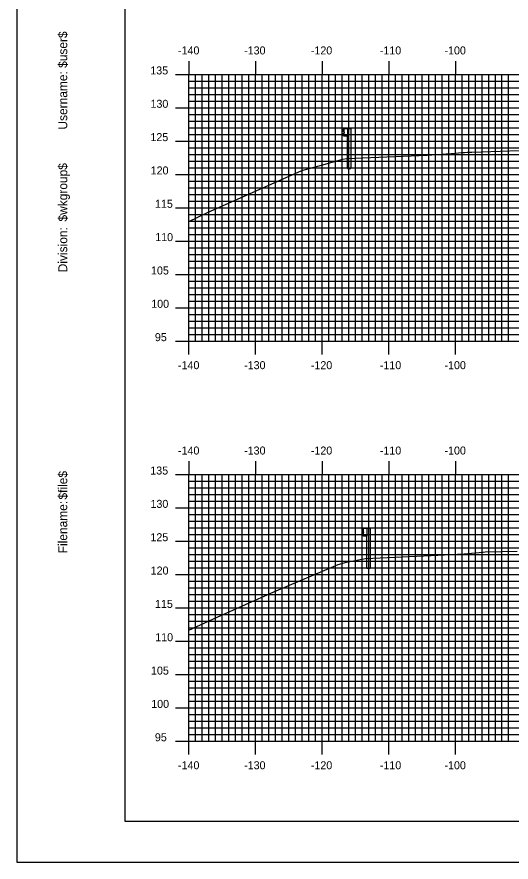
# Model space of a CAD drawing. Extents: x 858445 to 858788, y 364366 to 364586.
# Drawn here: x 858445.1 to 858519.2, y 364365.7 to 364492.4 of the extents above; entities that cross this region are included whole.
import ezdxf

# ---------------------------------------------------------------- set-up
doc = ezdxf.new("R2010")
doc.units = 0
for name, color, linetype in [('BORDER', 7, 'Continuous'), ('H_V ANNOTATION', 7, 'Continuous'), ('M_Guardrail', 7, 'Continuous'), ('M_Roadway_Centerline', 7, 'Continuous'), ('MAJOR', 7, 'Continuous'), ('MINOR', 7, 'Continuous'), ('PLOT BOUNDARY', 7, 'Continuous'), ('S_Roadway_Centerline', 7, 'Continuous')]:
    doc.layers.add(name, color=color, linetype=linetype)

msp = doc.modelspace()

# ---------------------------------------------------------------- linework, layer by layer
at = {"layer": 'BORDER'}
msp.add_lwpolyline([(858461.27, 364371.79), (858781.27, 364371.79), (858781.27, 364581.79), (858461.27, 364581.79)], close=True, dxfattribs=at)
at = {"layer": 'M_Guardrail'}
for p, q in [((858494.11, 364475.58), (858493.97, 364475.48)), ((858493.97, 364475.34), (858494.17, 364475.2)), ((858494.21, 364475.6), (858494.13, 364475.59)), ((858494.21, 364475.68), (858494.7, 364475.68)), ((858494.21, 364474.51), (858494.21, 364475.68)), ((858494.7, 364475.68), (858495.19, 364475.68)), ((858494.7, 364475.68), (858494.7, 364474.51)), ((858495.19, 364475.68), (858495.19, 364469.68)), ((858494.17, 364474.98), (858493.97, 364474.85)), ((858493.97, 364474.7), (858494.11, 364474.6)), ((858494.13, 364474.6), (858494.21, 364474.58)), ((858494.2, 364475.14), (858494.2, 364475.05)), ((858494.7, 364474.51), (858494.21, 364474.51)), ((858494.7, 364469.68), (858494.7, 364474.51)), ((858494.7, 364469.68), (858495.19, 364469.68)), ((858497.1, 364415.73), (858497.59, 364415.73)), ((858497.1, 364414.57), (858497.1, 364415.73)), ((858497.59, 364415.73), (858498.08, 364415.73)), ((858497.59, 364415.73), (858497.59, 364414.57)), ((858498.08, 364415.73), (858498.08, 364409.73)), ((858497, 364415.64), (858496.85, 364415.54)), ((858496.85, 364415.4), (858497.05, 364415.26)), ((858497.05, 364415.04), (858496.85, 364414.9)), ((858496.85, 364414.76), (858497, 364414.66)), ((858497.1, 364415.66), (858497.02, 364415.65)), ((858497.02, 364414.65), (858497.1, 364414.64)), ((858497.08, 364415.2), (858497.08, 364415.1)), ((858497.59, 364414.57), (858497.1, 364414.57)), ((858497.59, 364409.73), (858497.59, 364414.57)), ((858497.59, 364409.73), (858498.08, 364409.73))]:
    msp.add_line(p, q, dxfattribs=at)
for centre, major_axis, start_param, end_param in [((858494.02, 364475.41), (-0.0877, 0), 5.323254, 7.243116), ((858494.14, 364475.55), (-0.0417, 0), 4.886922, 5.323254), ((858494.02, 364474.78), (-0.0877, 0), 5.323254, 7.243116), ((858494.14, 364474.64), (-0.0417, 0), 0.959931, 1.396263), ((858494.12, 364475.14), (0.0789, 0), 0, 0.959931), ((858494.12, 364475.05), (0.0789, 0), 5.323254, 6.283185), ((858496.91, 364415.47), (-0.0877, 0), 5.323254, 7.243116), ((858496.91, 364414.83), (-0.0877, 0), 5.323254, 7.243116), ((858497.02, 364415.61), (-0.0417, 0), 4.886922, 5.323254), ((858497.02, 364414.69), (-0.0417, 0), 0.959931, 1.396263), ((858497, 364415.2), (0.0789, 0), 0, 0.959931), ((858497, 364415.1), (0.0789, 0), 5.323254, 6.283185)]:
    msp.add_ellipse(centre, major_axis=major_axis, ratio=0.995501, start_param=start_param, end_param=end_param, dxfattribs=at)
at = {"layer": 'MAJOR'}
for p, q in [((858470.87, 364485.79), (858470.87, 364483.79)), ((858480.87, 364485.79), (858480.87, 364483.79)), ((858490.87, 364485.79), (858490.87, 364483.79)), ((858500.87, 364485.79), (858500.87, 364483.79)), ((858510.87, 364485.79), (858510.87, 364483.79)), ((858468.87, 364483.79), (858470.87, 364483.79)), ((858470.87, 364483.79), (858750.87, 364483.79)), ((858470.87, 364443.79), (858470.87, 364483.79)), ((858470.87, 364443.79), (858470.87, 364483.79)), ((858470.87, 364483.79), (858750.87, 364483.79)), ((858480.87, 364443.79), (858480.87, 364483.79)), ((858490.87, 364443.79), (858490.87, 364483.79)), ((858500.87, 364443.79), (858500.87, 364483.79)), ((858510.87, 364443.79), (858510.87, 364483.79)), ((858468.87, 364478.79), (858470.87, 364478.79)), ((858470.87, 364478.79), (858750.87, 364478.79)), ((858468.87, 364473.79), (858470.87, 364473.79)), ((858470.87, 364473.79), (858750.87, 364473.79)), ((858468.87, 364468.79), (858470.87, 364468.79)), ((858470.87, 364468.79), (858750.87, 364468.79)), ((858468.87, 364463.79), (858470.87, 364463.79)), ((858470.87, 364463.79), (858750.87, 364463.79)), ((858468.87, 364458.79), (858470.87, 364458.79)), ((858470.87, 364458.79), (858750.87, 364458.79)), ((858468.87, 364453.79), (858470.87, 364453.79)), ((858470.87, 364453.79), (858750.87, 364453.79)), ((858468.87, 364448.79), (858470.87, 364448.79)), ((858470.87, 364448.79), (858750.87, 364448.79)), ((858468.87, 364443.79), (858470.87, 364443.79)), ((858470.87, 364443.79), (858750.87, 364443.79)), ((858470.87, 364443.79), (858750.87, 364443.79)), ((858470.87, 364441.78), (858470.87, 364443.79)), ((858480.87, 364441.78), (858480.87, 364443.79)), ((858490.87, 364441.78), (858490.87, 364443.79)), ((858500.87, 364441.78), (858500.87, 364443.79)), ((858510.87, 364441.78), (858510.87, 364443.79)), ((858470.87, 364425.79), (858470.87, 364423.79)), ((858480.87, 364425.79), (858480.87, 364423.79)), ((858490.87, 364425.79), (858490.87, 364423.79)), ((858500.87, 364425.79), (858500.87, 364423.79)), ((858510.87, 364425.79), (858510.87, 364423.79)), ((858468.87, 364423.79), (858470.87, 364423.79)), ((858470.87, 364423.79), (858750.87, 364423.79)), ((858470.87, 364383.79), (858470.87, 364423.79)), ((858470.87, 364383.79), (858470.87, 364423.79)), ((858470.87, 364423.79), (858750.87, 364423.79)), ((858480.87, 364383.79), (858480.87, 364423.79)), ((858490.87, 364383.79), (858490.87, 364423.79)), ((858500.87, 364383.79), (858500.87, 364423.79)), ((858510.87, 364383.79), (858510.87, 364423.79)), ((858468.87, 364418.79), (858470.87, 364418.79)), ((858470.87, 364418.79), (858750.87, 364418.79)), ((858468.87, 364413.79), (858470.87, 364413.79)), ((858470.87, 364413.79), (858750.87, 364413.79)), ((858468.87, 364408.79), (858470.87, 364408.79)), ((858470.87, 364408.79), (858750.87, 364408.79)), ((858468.87, 364403.79), (858470.87, 364403.79)), ((858470.87, 364403.79), (858750.87, 364403.79)), ((858468.87, 364398.79), (858470.87, 364398.79)), ((858470.87, 364398.79), (858750.87, 364398.79)), ((858468.87, 364393.79), (858470.87, 364393.79)), ((858470.87, 364393.79), (858750.87, 364393.79)), ((858468.87, 364388.79), (858470.87, 364388.79)), ((858470.87, 364388.79), (858750.87, 364388.79)), ((858468.87, 364383.79), (858470.87, 364383.79)), ((858470.87, 364383.79), (858750.87, 364383.79)), ((858470.87, 364383.79), (858750.87, 364383.79)), ((858470.87, 364381.78), (858470.87, 364383.79)), ((858480.87, 364381.78), (858480.87, 364383.79)), ((858490.87, 364381.78), (858490.87, 364383.79)), ((858500.87, 364381.78), (858500.87, 364383.79)), ((858510.87, 364381.78), (858510.87, 364383.79))]:
    msp.add_line(p, q, dxfattribs=at)
at = {"layer": 'MINOR'}
for p, q in [((858471.87, 364443.79), (858471.87, 364483.79)), ((858472.87, 364443.79), (858472.87, 364483.79)), ((858473.87, 364443.79), (858473.87, 364483.79)), ((858474.87, 364443.79), (858474.87, 364483.79)), ((858475.87, 364443.79), (858475.87, 364483.79)), ((858476.87, 364443.79), (858476.87, 364483.79)), ((858477.87, 364443.79), (858477.87, 364483.79)), ((858478.87, 364443.79), (858478.87, 364483.79)), ((858479.87, 364443.79), (858479.87, 364483.79)), ((858481.87, 364443.79), (858481.87, 364483.79)), ((858482.87, 364443.79), (858482.87, 364483.79)), ((858483.87, 364443.79), (858483.87, 364483.79)), ((858484.87, 364443.79), (858484.87, 364483.79)), ((858485.87, 364443.79), (858485.87, 364483.79)), ((858486.87, 364443.79), (858486.87, 364483.79)), ((858487.87, 364443.79), (858487.87, 364483.79)), ((858488.87, 364443.79), (858488.87, 364483.79)), ((858489.87, 364443.79), (858489.87, 364483.79)), ((858491.87, 364443.79), (858491.87, 364483.79)), ((858492.87, 364443.79), (858492.87, 364483.79)), ((858493.87, 364443.79), (858493.87, 364483.79)), ((858494.87, 364443.79), (858494.87, 364483.79)), ((858495.87, 364443.79), (858495.87, 364483.79)), ((858496.87, 364443.79), (858496.87, 364483.79)), ((858497.87, 364443.79), (858497.87, 364483.79)), ((858498.87, 364443.79), (858498.87, 364483.79)), ((858499.87, 364443.79), (858499.87, 364483.79)), ((858501.87, 364443.79), (858501.87, 364483.79)), ((858502.87, 364443.79), (858502.87, 364483.79)), ((858503.87, 364443.79), (858503.87, 364483.79)), ((858504.87, 364443.79), (858504.87, 364483.79)), ((858505.87, 364443.79), (858505.87, 364483.79)), ((858506.87, 364443.79), (858506.87, 364483.79)), ((858507.87, 364443.79), (858507.87, 364483.79)), ((858508.87, 364443.79), (858508.87, 364483.79)), ((858509.87, 364443.79), (858509.87, 364483.79)), ((858511.87, 364443.79), (858511.87, 364483.79)), ((858512.87, 364443.79), (858512.87, 364483.79)), ((858513.87, 364443.79), (858513.87, 364483.79)), ((858514.87, 364443.79), (858514.87, 364483.79)), ((858515.87, 364443.79), (858515.87, 364483.79)), ((858516.87, 364443.79), (858516.87, 364483.79)), ((858517.87, 364443.79), (858517.87, 364483.79)), ((858518.87, 364443.79), (858518.87, 364483.79)), ((858470.87, 364482.79), (858750.87, 364482.79)), ((858470.87, 364482.79), (858472.88, 364482.79)), ((858470.87, 364481.79), (858750.87, 364481.79)), ((858470.87, 364481.79), (858472.88, 364481.79)), ((858470.87, 364480.79), (858750.87, 364480.79)), ((858470.87, 364480.79), (858472.88, 364480.79)), ((858470.87, 364479.79), (858750.87, 364479.79)), ((858470.87, 364479.79), (858472.88, 364479.79)), ((858470.87, 364477.79), (858750.87, 364477.79)), ((858470.87, 364477.79), (858472.88, 364477.79)), ((858470.87, 364476.79), (858750.87, 364476.79)), ((858470.87, 364476.79), (858472.88, 364476.79)), ((858470.87, 364475.79), (858750.87, 364475.79)), ((858470.87, 364475.79), (858472.88, 364475.79)), ((858470.87, 364474.79), (858750.87, 364474.79)), ((858470.87, 364474.79), (858472.88, 364474.79)), ((858470.87, 364472.79), (858750.87, 364472.79)), ((858470.87, 364472.79), (858472.88, 364472.79)), ((858470.87, 364471.79), (858750.87, 364471.79)), ((858470.87, 364471.79), (858472.88, 364471.79)), ((858470.87, 364470.79), (858750.87, 364470.79)), ((858470.87, 364470.79), (858472.88, 364470.79)), ((858470.87, 364469.79), (858750.87, 364469.79)), ((858470.87, 364469.79), (858472.88, 364469.79)), ((858470.87, 364467.79), (858750.87, 364467.79)), ((858470.87, 364467.79), (858472.88, 364467.79)), ((858470.87, 364466.79), (858750.87, 364466.79)), ((858470.87, 364466.79), (858472.88, 364466.79)), ((858470.87, 364465.79), (858750.87, 364465.79)), ((858470.87, 364465.79), (858472.88, 364465.79)), ((858470.87, 364464.79), (858750.87, 364464.79)), ((858470.87, 364464.79), (858472.88, 364464.79)), ((858470.87, 364462.79), (858750.87, 364462.79)), ((858470.87, 364462.79), (858472.88, 364462.79)), ((858470.87, 364461.79), (858750.87, 364461.79)), ((858470.87, 364461.79), (858472.88, 364461.79)), ((858470.87, 364460.79), (858750.87, 364460.79)), ((858470.87, 364460.79), (858472.88, 364460.79)), ((858470.87, 364459.79), (858750.87, 364459.79)), ((858470.87, 364459.79), (858472.88, 364459.79)), ((858470.87, 364457.79), (858750.87, 364457.79)), ((858470.87, 364457.79), (858472.88, 364457.79)), ((858470.87, 364456.79), (858750.87, 364456.79)), ((858470.87, 364456.79), (858472.88, 364456.79)), ((858470.87, 364455.79), (858750.87, 364455.79)), ((858470.87, 364455.79), (858472.88, 364455.79)), ((858470.87, 364454.79), (858750.87, 364454.79)), ((858470.87, 364454.79), (858472.88, 364454.79)), ((858470.87, 364452.79), (858750.87, 364452.79)), ((858470.87, 364452.79), (858472.88, 364452.79)), ((858470.87, 364451.79), (858750.87, 364451.79)), ((858470.87, 364451.79), (858472.88, 364451.79)), ((858470.87, 364450.79), (858750.87, 364450.79)), ((858470.87, 364450.79), (858472.88, 364450.79)), ((858470.87, 364449.79), (858750.87, 364449.79)), ((858470.87, 364449.79), (858472.88, 364449.79)), ((858470.87, 364447.79), (858750.87, 364447.79)), ((858470.87, 364447.79), (858472.88, 364447.79)), ((858470.87, 364446.79), (858750.87, 364446.79)), ((858470.87, 364446.79), (858472.88, 364446.79)), ((858470.87, 364445.79), (858750.87, 364445.79)), ((858470.87, 364445.79), (858472.88, 364445.79)), ((858470.87, 364444.79), (858750.87, 364444.79)), ((858470.87, 364444.79), (858472.88, 364444.79)), ((858471.87, 364383.79), (858471.87, 364423.79)), ((858472.87, 364383.79), (858472.87, 364423.79)), ((858473.87, 364383.79), (858473.87, 364423.79)), ((858474.87, 364383.79), (858474.87, 364423.79)), ((858475.87, 364383.79), (858475.87, 364423.79)), ((858476.87, 364383.79), (858476.87, 364423.79)), ((858477.87, 364383.79), (858477.87, 364423.79)), ((858478.87, 364383.79), (858478.87, 364423.79)), ((858479.87, 364383.79), (858479.87, 364423.79)), ((858481.87, 364383.79), (858481.87, 364423.79)), ((858482.87, 364383.79), (858482.87, 364423.79)), ((858483.87, 364383.79), (858483.87, 364423.79)), ((858484.87, 364383.79), (858484.87, 364423.79)), ((858485.87, 364383.79), (858485.87, 364423.79)), ((858486.87, 364383.79), (858486.87, 364423.79)), ((858487.87, 364383.79), (858487.87, 364423.79)), ((858488.87, 364383.79), (858488.87, 364423.79)), ((858489.87, 364383.79), (858489.87, 364423.79)), ((858491.87, 364383.79), (858491.87, 364423.79)), ((858492.87, 364383.79), (858492.87, 364423.79)), ((858493.87, 364383.79), (858493.87, 364423.79)), ((858494.87, 364383.79), (858494.87, 364423.79)), ((858495.87, 364383.79), (858495.87, 364423.79)), ((858496.87, 364383.79), (858496.87, 364423.79)), ((858497.87, 364383.79), (858497.87, 364423.79)), ((858498.87, 364383.79), (858498.87, 364423.79)), ((858499.87, 364383.79), (858499.87, 364423.79)), ((858501.87, 364383.79), (858501.87, 364423.79)), ((858502.87, 364383.79), (858502.87, 364423.79)), ((858503.87, 364383.79), (858503.87, 364423.79)), ((858504.87, 364383.79), (858504.87, 364423.79)), ((858505.87, 364383.79), (858505.87, 364423.79)), ((858506.87, 364383.79), (858506.87, 364423.79)), ((858507.87, 364383.79), (858507.87, 364423.79)), ((858508.87, 364383.79), (858508.87, 364423.79)), ((858509.87, 364383.79), (858509.87, 364423.79)), ((858511.87, 364383.79), (858511.87, 364423.79)), ((858512.87, 364383.79), (858512.87, 364423.79)), ((858513.87, 364383.79), (858513.87, 364423.79)), ((858514.87, 364383.79), (858514.87, 364423.79)), ((858515.87, 364383.79), (858515.87, 364423.79)), ((858516.87, 364383.79), (858516.87, 364423.79)), ((858517.87, 364383.79), (858517.87, 364423.79)), ((858518.87, 364383.79), (858518.87, 364423.79)), ((858470.87, 364422.79), (858750.87, 364422.79)), ((858470.87, 364422.79), (858472.88, 364422.79)), ((858470.87, 364421.79), (858750.87, 364421.79)), ((858470.87, 364421.79), (858472.88, 364421.79)), ((858470.87, 364420.79), (858750.87, 364420.79)), ((858470.87, 364420.79), (858472.88, 364420.79)), ((858470.87, 364419.79), (858750.87, 364419.79)), ((858470.87, 364419.79), (858472.88, 364419.79)), ((858470.87, 364417.79), (858750.87, 364417.79)), ((858470.87, 364417.79), (858472.88, 364417.79)), ((858470.87, 364416.79), (858750.87, 364416.79)), ((858470.87, 364416.79), (858472.88, 364416.79)), ((858470.87, 364415.79), (858750.87, 364415.79)), ((858470.87, 364415.79), (858472.88, 364415.79)), ((858470.87, 364414.79), (858750.87, 364414.79)), ((858470.87, 364414.79), (858472.88, 364414.79)), ((858470.87, 364412.79), (858750.87, 364412.79)), ((858470.87, 364412.79), (858472.88, 364412.79)), ((858470.87, 364411.79), (858750.87, 364411.79)), ((858470.87, 364411.79), (858472.88, 364411.79)), ((858470.87, 364410.79), (858750.87, 364410.79)), ((858470.87, 364410.79), (858472.88, 364410.79)), ((858470.87, 364409.79), (858750.87, 364409.79)), ((858470.87, 364409.79), (858472.88, 364409.79)), ((858470.87, 364407.79), (858750.87, 364407.79)), ((858470.87, 364407.79), (858472.88, 364407.79)), ((858470.87, 364406.79), (858750.87, 364406.79)), ((858470.87, 364406.79), (858472.88, 364406.79)), ((858470.87, 364405.79), (858750.87, 364405.79)), ((858470.87, 364405.79), (858472.88, 364405.79)), ((858470.87, 364404.79), (858750.87, 364404.79)), ((858470.87, 364404.79), (858472.88, 364404.79)), ((858470.87, 364402.79), (858750.87, 364402.79)), ((858470.87, 364402.79), (858472.88, 364402.79)), ((858470.87, 364401.79), (858750.87, 364401.79)), ((858470.87, 364401.79), (858472.88, 364401.79)), ((858470.87, 364400.79), (858750.87, 364400.79)), ((858470.87, 364400.79), (858472.88, 364400.79)), ((858470.87, 364399.79), (858750.87, 364399.79)), ((858470.87, 364399.79), (858472.88, 364399.79)), ((858470.87, 364397.79), (858750.87, 364397.79)), ((858470.87, 364397.79), (858472.88, 364397.79)), ((858470.87, 364396.79), (858750.87, 364396.79)), ((858470.87, 364396.79), (858472.88, 364396.79)), ((858470.87, 364395.79), (858750.87, 364395.79)), ((858470.87, 364395.79), (858472.88, 364395.79)), ((858470.87, 364394.79), (858750.87, 364394.79)), ((858470.87, 364394.79), (858472.88, 364394.79)), ((858470.87, 364392.79), (858750.87, 364392.79)), ((858470.87, 364392.79), (858472.88, 364392.79)), ((858470.87, 364391.79), (858750.87, 364391.79)), ((858470.87, 364391.79), (858472.88, 364391.79)), ((858470.87, 364390.79), (858750.87, 364390.79)), ((858470.87, 364390.79), (858472.88, 364390.79)), ((858470.87, 364389.79), (858750.87, 364389.79)), ((858470.87, 364389.79), (858472.88, 364389.79)), ((858470.87, 364387.79), (858750.87, 364387.79)), ((858470.87, 364387.79), (858472.88, 364387.79)), ((858470.87, 364386.79), (858750.87, 364386.79)), ((858470.87, 364386.79), (858472.88, 364386.79)), ((858470.87, 364385.79), (858750.87, 364385.79)), ((858470.87, 364385.79), (858472.88, 364385.79)), ((858470.87, 364384.79), (858750.87, 364384.79)), ((858470.87, 364384.79), (858472.88, 364384.79))]:
    msp.add_line(p, q, dxfattribs=at)
at = {"layer": 'PLOT BOUNDARY'}
msp.add_lwpolyline([(858445.09, 364365.67), (858785.09, 364365.67), (858785.09, 364585.67), (858445.09, 364585.67)], close=True, dxfattribs=at)
at = {"layer": 'S_Roadway_Centerline'}
for points in [[(858470.87, 364461.71), (858473.68, 364463.1), (858487.86, 364469.37), (858490.79, 364470.19), (858493.97, 364471.06), (858494.56, 364471.18), (858498.19, 364471.35), (858506.66, 364471.66), (858510.92, 364472), (858511.72, 364472.06), (858512.26, 364472.1), (858512.64, 364472.12), (858513.32, 364472.15), (858524.69, 364472.55)], [(858470.87, 364400.47), (858475.14, 364402.38), (858483.62, 364406.18), (858493.27, 364410.3), (858494.53, 364410.65), (858497.37, 364411.2), (858507.26, 364411.66), (858512.21, 364411.9), (858515.01, 364412.15), (858515.06, 364412.17), (858515.33, 364412.18), (858520.16, 364412.31)]]:
    msp.add_lwpolyline(points, dxfattribs=at)

# ---------------------------------------------------------------- texts
at = {"layer": 'BORDER'}
for s, p in [('$user$', (858452.64, 364484.77)), ('Username:', (858452.64, 364475.52)), ('$wkgroup$', (858452.64, 364461.73)), ('Division:', (858452.64, 364454.12)), ('$file$', (858452.64, 364420.04)), ('Filename:', (858452.64, 364411.98))]:
    msp.add_text(s, height=1.339, rotation=90, dxfattribs=at).set_placement(p)
at = {"layer": 'H_V ANNOTATION'}
for s, p in [('-140', (858469.26, 364486.79)), ('-130', (858479.18, 364486.79)), ('-120', (858489.19, 364486.79)), ('-110', (858499.54, 364486.79)), ('-100', (858509.24, 364486.79)), ('135', (858465.1, 364483.79)), ('130', (858465.13, 364478.79)), ('125', (858465.12, 364473.79)), ('120', (858465.16, 364468.79)), ('115', (858465.81, 364463.79)), ('110', (858465.84, 364458.79)), ('105', (858465.21, 364453.79)), ('100', (858465.24, 364448.79)), ('95', (858465.79, 364443.79)), ('-140', (858469.26, 364439.59)), ('-130', (858479.18, 364439.59)), ('-120', (858489.19, 364439.59)), ('-110', (858499.54, 364439.59)), ('-100', (858509.24, 364439.59)), ('-140', (858469.26, 364426.79)), ('-130', (858479.18, 364426.79)), ('-120', (858489.19, 364426.79)), ('-110', (858499.54, 364426.79)), ('-100', (858509.24, 364426.79)), ('135', (858465.1, 364423.79)), ('130', (858465.13, 364418.79)), ('125', (858465.12, 364413.79)), ('120', (858465.16, 364408.79)), ('115', (858465.81, 364403.79)), ('110', (858465.84, 364398.79)), ('105', (858465.21, 364393.79)), ('100', (858465.24, 364388.79)), ('95', (858465.79, 364383.79)), ('-140', (858469.26, 364379.59)), ('-130', (858479.18, 364379.59)), ('-120', (858489.19, 364379.59)), ('-110', (858499.54, 364379.59)), ('-100', (858509.24, 364379.59))]:
    msp.add_text(s, height=1.2, dxfattribs=at).set_placement(p)
at = {"layer": 'M_Roadway_Centerline'}
for s, p in [('C', (858512.26, 364472.1)), ('L', (858512.26, 364472.09)), ('C', (858515.06, 364412.17)), ('L', (858515.06, 364412.17))]:
    msp.add_text(s, height=0.0146, dxfattribs=at).set_placement(p)
at = {"layer": 'MAJOR'}
for p in [(858470.87, 364443.79), (858470.87, 364383.79)]:
    msp.add_text('-', height=0.012, dxfattribs=at).set_placement(p)

doc.saveas('drawing.dxf')
